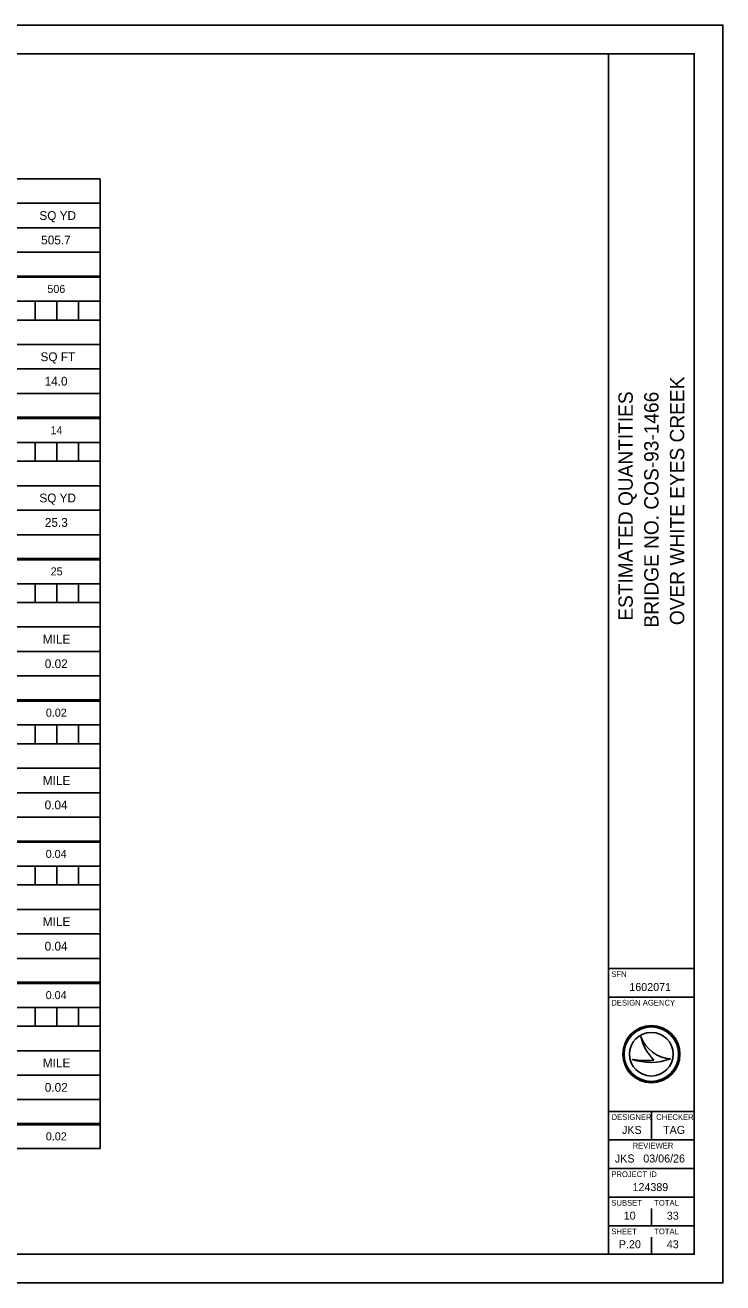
# Model space of a CAD drawing. Extents: x 0 to 34, y 0 to 22.
# Drawn here: x 21.8 to 34, y 0 to 22 of the extents above; entities that cross this region are included whole.
import ezdxf

# ---------------------------------------------------------------- set-up
doc = ezdxf.new("R2010")
doc.units = 0
for name, color, linetype in [('Default', 7, 'Continuous'), ('SH_Border', 7, 'Continuous'), ('SH_Cut_Line', 7, 'Continuous'), ('SH_Data', 7, 'Continuous')]:
    doc.layers.add(name, color=color, linetype=linetype)

msp = doc.modelspace()

# ---------------------------------------------------------------- linework, layer by layer
at = {"layer": 'Default'}
for p, q in [((9.504, 19.313), (23.109, 19.313)), ((23.109, 19.313), (23.109, 17.589)), ((9.504, 18.885), (23.109, 18.885)), ((9.504, 18.456), (23.109, 18.456)), ((9.504, 18.028), (23.109, 18.028)), ((9.504, 17.611), (23.109, 17.611)), ((23.109, 17.611), (23.109, 15.118)), ((9.504, 17.589), (23.109, 17.589)), ((9.504, 17.172), (23.109, 17.172)), ((9.504, 16.842), (23.109, 16.842)), ((9.504, 16.414), (23.109, 16.414)), ((9.504, 15.986), (23.109, 15.986)), ((9.504, 15.557), (23.109, 15.557)), ((9.504, 15.14), (23.109, 15.14)), ((9.504, 15.118), (23.109, 15.118)), ((23.109, 15.14), (23.109, 12.648)), ((9.504, 14.701), (23.109, 14.701)), ((9.504, 14.372), (23.109, 14.372)), ((9.504, 13.943), (23.109, 13.943)), ((9.504, 13.515), (23.109, 13.515)), ((9.504, 13.087), (23.109, 13.087)), ((9.504, 12.67), (23.109, 12.67)), ((9.504, 12.648), (23.109, 12.648)), ((23.109, 12.67), (23.109, 10.177)), ((9.504, 12.23), (23.109, 12.23)), ((9.504, 11.901), (23.109, 11.901)), ((9.504, 11.473), (23.109, 11.473)), ((9.504, 11.045), (23.109, 11.045)), ((9.504, 10.616), (23.109, 10.616)), ((9.504, 10.199), (23.109, 10.199)), ((9.504, 10.177), (23.109, 10.177)), ((23.109, 10.199), (23.109, 7.707)), ((9.504, 9.76), (23.109, 9.76)), ((9.504, 9.43), (23.109, 9.43)), ((9.504, 9.002), (23.109, 9.002)), ((9.504, 8.574), (23.109, 8.574)), ((9.504, 8.146), (23.109, 8.146)), ((9.504, 7.728), (23.109, 7.728)), ((9.504, 7.707), (23.109, 7.707)), ((23.109, 7.728), (23.109, 5.236)), ((9.504, 7.289), (23.109, 7.289)), ((9.504, 6.96), (23.109, 6.96)), ((9.504, 6.532), (23.109, 6.532)), ((9.504, 6.103), (23.109, 6.103)), ((9.504, 5.675), (23.109, 5.675)), ((9.504, 5.258), (23.109, 5.258)), ((9.504, 5.236), (23.109, 5.236)), ((23.109, 5.258), (23.109, 2.765)), ((9.504, 4.819), (23.109, 4.819)), ((9.504, 4.489), (23.109, 4.489)), ((9.504, 4.061), (23.109, 4.061)), ((9.504, 3.633), (23.109, 3.633)), ((9.504, 3.205), (23.109, 3.205)), ((9.504, 2.787), (23.109, 2.787)), ((9.504, 2.765), (23.109, 2.765)), ((23.109, 2.787), (23.109, 2.348)), ((9.504, 2.348), (23.109, 2.348))]:
    msp.add_line(p, q, dxfattribs=at)
for points in [[(21.594, 17.172), (21.972, 17.172), (21.972, 16.842), (21.594, 16.842)], [(21.972, 17.172), (22.351, 17.172), (22.351, 16.842), (21.972, 16.842)], [(22.351, 17.172), (22.73, 17.172), (22.73, 16.842), (22.351, 16.842)], [(22.73, 17.172), (23.109, 17.172), (23.109, 16.842), (22.73, 16.842)], [(21.594, 14.701), (21.972, 14.701), (21.972, 14.372), (21.594, 14.372)], [(21.972, 14.701), (22.351, 14.701), (22.351, 14.372), (21.972, 14.372)], [(22.351, 14.701), (22.73, 14.701), (22.73, 14.372), (22.351, 14.372)], [(22.73, 14.701), (23.109, 14.701), (23.109, 14.372), (22.73, 14.372)], [(21.594, 12.23), (21.972, 12.23), (21.972, 11.901), (21.594, 11.901)], [(21.972, 12.23), (22.351, 12.23), (22.351, 11.901), (21.972, 11.901)], [(22.351, 12.23), (22.73, 12.23), (22.73, 11.901), (22.351, 11.901)], [(22.73, 12.23), (23.109, 12.23), (23.109, 11.901), (22.73, 11.901)], [(21.594, 9.76), (21.972, 9.76), (21.972, 9.43), (21.594, 9.43)], [(21.972, 9.76), (22.351, 9.76), (22.351, 9.43), (21.972, 9.43)], [(22.351, 9.76), (22.73, 9.76), (22.73, 9.43), (22.351, 9.43)], [(22.73, 9.76), (23.109, 9.76), (23.109, 9.43), (22.73, 9.43)], [(21.594, 7.289), (21.972, 7.289), (21.972, 6.96), (21.594, 6.96)], [(21.972, 7.289), (22.351, 7.289), (22.351, 6.96), (21.972, 6.96)], [(22.351, 7.289), (22.73, 7.289), (22.73, 6.96), (22.351, 6.96)], [(22.73, 7.289), (23.109, 7.289), (23.109, 6.96), (22.73, 6.96)], [(21.594, 4.819), (21.972, 4.819), (21.972, 4.489), (21.594, 4.489)], [(21.972, 4.819), (22.351, 4.819), (22.351, 4.489), (21.972, 4.489)], [(22.351, 4.819), (22.73, 4.819), (22.73, 4.489), (22.351, 4.489)], [(22.73, 4.819), (23.109, 4.819), (23.109, 4.489), (22.73, 4.489)]]:
    msp.add_lwpolyline(points, close=True, dxfattribs=at)
at = {"layer": 'SH_Border'}
for p, q in [((32, 0.5), (32, 21.5)), ((32, 5.5), (33.5, 5.5)), ((32, 5), (33.5, 5)), ((32, 3), (33.5, 3)), ((32.75, 3), (32.75, 2.5)), ((32, 2.5), (33.5, 2.5)), ((32, 2), (33.5, 2)), ((32, 1.5), (33.5, 1.5)), ((32, 1), (33.5, 1))]:
    msp.add_line(p, q, dxfattribs=at)
msp.add_lwpolyline([(1.5, 21.5), (33.5, 21.5), (33.5, 0.5), (1.5, 0.5)], close=True, dxfattribs=at)
at = {"layer": 'SH_Cut_Line'}
msp.add_lwpolyline([(0, 0), (34, 0), (34, 22), (0, 22)], close=True, dxfattribs=at)
at = {"layer": 'SH_Data'}
for p, q in [((32.567, 4.31), (32.567, 4.31)), ((32.75, 4), (32.75, 4)), ((32.417, 3.91), (32.417, 3.91)), ((33.087, 3.919), (33.087, 3.919)), ((32.75, 1), (32.75, 1.3)), ((32.375, 0.675), (32.375, 0.675)), ((32.75, 0.5), (32.75, 0.8))]:
    msp.add_line(p, q, dxfattribs=at)
for radius in [0.5, 0.477, 0.477, 0.382]:
    msp.add_circle((32.75, 4), radius, dxfattribs=at)
for centre, radius, start, end in [((33.116, 4.498), 0.58, 198.9257, 198.9319), ((33.347, 4.47), 0.796, 191.6379, 191.6421), ((33.116, 4.498), 0.58, 198.9319, 267.1657), ((33.347, 4.47), 0.796, 191.6421, 226.0947), ((32.739, 4.87), 1.013, 251.4576, 290.0832), ((32.648, 5.154), 1.266, 259.4964, 259.4995), ((32.739, 4.87), 1.013, 251.4527, 251.4576), ((32.648, 5.154), 1.266, 259.4995, 276.6672)]:
    msp.add_arc(centre, radius, start, end, dxfattribs=at)

# ---------------------------------------------------------------- texts
at = {"layer": 'Default'}
for s, height, p in [('SQ YD', 0.154, (22.048, 18.593)), ('505.7', 0.154, (22.08, 18.165)), ('506', 0.14, (22.188, 17.316)), ('SQ FT', 0.154, (22.068, 16.123)), ('14.0', 0.154, (22.14, 15.695)), ('14', 0.14, (22.243, 14.845)), ('SQ YD', 0.154, (22.048, 13.652)), ('25.3', 0.154, (22.144, 13.224)), ('25', 0.14, (22.246, 12.375)), ('MILE', 0.154, (22.108, 11.182)), ('0.02', 0.154, (22.143, 10.753)), ('0.02', 0.14, (22.162, 9.904)), ('MILE', 0.154, (22.108, 8.711)), ('0.04', 0.154, (22.14, 8.283)), ('0.04', 0.14, (22.159, 7.433)), ('MILE', 0.154, (22.108, 6.24)), ('0.04', 0.154, (22.14, 5.812)), ('0.04', 0.14, (22.159, 4.963)), ('MILE', 0.154, (22.108, 3.77)), ('0.02', 0.154, (22.143, 3.342)), ('0.02', 0.14, (22.162, 2.492))]:
    msp.add_text(s, height=height, dxfattribs=at).set_placement(p)
at = {"layer": 'SH_Data'}
for s, p in [('OVER WHITE EYES CREEK', (33.325, 11.505)), ('ESTIMATED QUANTITIES', (32.425, 11.582)), ('BRIDGE NO. COS-93-1466', (32.875, 11.463))]:
    msp.add_text(s, height=0.25, rotation=90, dxfattribs=at).set_placement(p)
for s, height, p in [('SFN', 0.1, (32.05, 5.35)), ('1602071', 0.14, (32.365, 5.105)), ('DESIGN AGENCY', 0.1, (32.05, 4.85)), ('DESIGNER', 0.1, (32.054, 2.85)), ('CHECKER', 0.1, (32.835, 2.85)), ('JKS', 0.14, (32.237, 2.605)), ('TAG', 0.14, (32.955, 2.605)), ('REVIEWER', 0.1, (32.422, 2.35)), ('JKS', 0.14, (32.112, 2.105)), ('03/06/26', 0.14, (32.609, 2.105)), ('PROJECT ID', 0.1, (32.05, 1.85)), ('124389', 0.14, (32.42, 1.605)), ('SUBSET', 0.1, (32.05, 1.35)), ('TOTAL', 0.1, (32.8, 1.35)), ('10', 0.14, (32.267, 1.105)), ('33', 0.14, (33.02, 1.105)), ('SHEET', 0.1, (32.05, 0.85)), ('TOTAL', 0.1, (32.8, 0.85)), ('P.20', 0.14, (32.182, 0.605)), ('43', 0.14, (33.02, 0.605))]:
    msp.add_text(s, height=height, dxfattribs=at).set_placement(p)

doc.saveas('drawing.dxf')
